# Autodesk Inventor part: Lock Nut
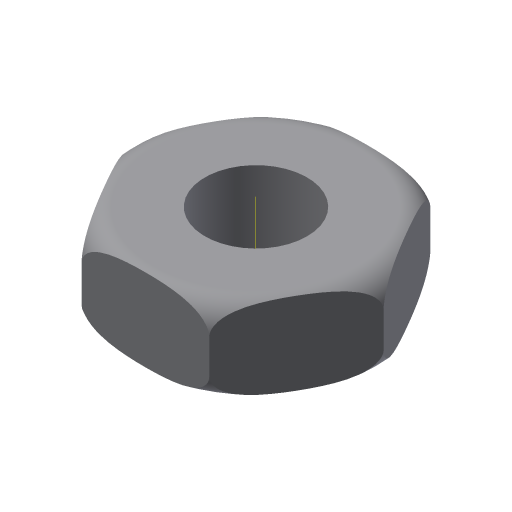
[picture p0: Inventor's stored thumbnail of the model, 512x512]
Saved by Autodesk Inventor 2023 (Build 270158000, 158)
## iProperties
Created: 2009-04
Part Number: Lock Nut
Document SubType Name: Modeling
Designer: Sham
Density: 1 g/cm^3
Material: Generic
Appearance: Default
Author: Sham
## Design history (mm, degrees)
sketch "Sketch1"
  geometry: L1 (7.5, 12.99)-(15, 0); L2 (15, 0)-(7.5, -12.99); L3 (7.5, -12.99)-(-7.5, -12.99); L4 (-7.5, -12.99)-(-15, 0); L5 (-15, 0)-(-7.5, 12.99); L6 (-7.5, 12.99)-(7.5, 12.99); C1 r 6 at (0, 0); 1 further point
  constraints: 12 end point, 1 centre point, 1 coincident, 13 other
  dimensions: "d0" = 30 distance of L1.end L4.end; "d1" = 12 diameter of C1
extrude "Extrusion1" new body sketch "Sketch1" distance "d2" = 10; taper "d3" = 0 deg
sketch "Sketch2"
  geometry: L1 (-12, 0)-(-12, -0.022); L2 (-15, 7)-(-15, 3); L3 (0, -2.87)-(0, 12.87) reference; A1 r 3 centre (-12, 7) between (-12, 10) and (-15, 7); A2 r 3 centre (-12, 3) between (-15, 3) and (-12, 0)
  constraints: 4 end point, 4 point on circle, 2 centre point, 1 tangent
revolve "Revolution1" sketch "Sketch2" stored, may be unused: angle "d7" = 90 deg
body "Solid1"
other parameters: "d6" = 90 deg
